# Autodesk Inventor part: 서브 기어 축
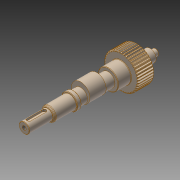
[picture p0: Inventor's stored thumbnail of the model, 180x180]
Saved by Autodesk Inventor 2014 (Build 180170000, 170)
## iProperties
Created: 2018-12
Part Number: 서브 기어 축
Material: 강철, 연강
Document SubType Name: Modeling
Designer: mduedu
Categories: <?xml version="1.0" encoding="UTF-16"?> <MemberInstance><Categories><FamilyTemplate><FamilyTemplateParameter ValueType="xs:double" Id="1" ObjectReferenceKey="da
Density: 7.86 g/cm^3
Mass: 484.999 g
Surface Area: 155.103 cm^2
Volume: 61.7047 cm^3
Appearance: 기본값(1)
Author: mduedu
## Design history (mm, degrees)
sketch "Sketch1"
  geometry: C1 r 21.3 at (0, 0)
  constraints: 1 centre point
  dimensions: "d0" = 42.6 diameter of C1 (= da_da)
extrude "Extrusion1" new body sketch "Sketch1" distance "d1" = 20 (= da_b); taper "d2" = 0 deg
workplane "Work Plane2"
sketch "Sketch2"
  geometry: C1 r 21.3 at (0, 0) reference; C2 r 20.5 at (0, 0)
  constraints: 1 centre point, 1 coincident
  dimensions: "d3" = 41 diameter of C2 (= da_dw)
feature "피치 지름" sketch "Sketch2" dims "d4" = 10, "d5" = 0
workplane "Work Plane8"
workplane "Work Plane9"
chamfer "모따기1" distance "d49" = 1; stored, may be unused: second distance "d50" = 2, angle "d51" = 45 deg
sketch "스케치3"
  geometry: C1 r 12.5 at (0, 0); 1 further point
  constraints: 1 centre point, 1 coincident
  dimensions: "d52" = 25 diameter of C1
extrude "돌출2" join sketch "스케치3" distance "d53" = 16; taper "d54" = 0 deg
sketch "스케치4"
  geometry: C1 r 8.5 at (0, 0); 1 further point
  constraints: 1 centre point, 1 coincident
  dimensions: "d55" = 17 diameter of C1
extrude "돌출3" join sketch "스케치4" distance "d56" = 104; taper "d57" = 0 deg
sketch "스케치5"
  geometry: C1 r 7.5 at (0, 0); 1 further point
  constraints: 1 centre point, 1 coincident
  dimensions: "d58" = 15 diameter of C1
extrude "돌출4" join sketch "스케치5" distance "d59" = 16; taper "d60" = 0 deg
sketch "스케치6"
  geometry: C1 r 4 at (0, 0); 1 further point
  constraints: 1 centre point, 1 coincident
  dimensions: "d61" = 8 diameter of C1
extrude "돌출5" join sketch "스케치6" distance "d62" = 7; taper "d63" = 0 deg
fillet "모깎기1" dims "d67" = 0.5
feature "스퍼 기어" dims "da_b" = 20, "da_d" = 41, "da_aw" = 31, "da_da" = 42.6, "da_df" = 39.086, "da_dw" = 41, angle "da_beta" = 0 deg, "da_lefttooth" = 0, "da_righttooth" = 0
node "작업 평면11"
sketch "스케치7"
  geometry: C1 r 11.5 at (0, 3); C2 r 8.5 at (0, 0) reference; 1 further point
  constraints: 1 centre point, 1 tangent, 1 vertical alignment
  dimensions: "d69" = 3 distance of point (0, 0) C1.centre; "d70" = 23 diameter of C1 (derived)
extrude "돌출6" join sketch "스케치7" stored distance "d71" = 20; taper "d72" = 0 deg
node "작업 평면12"
sketch "스케치8"
  geometry: C1 r 12.5 at (0, 0) reference; C2 r 10 at (0, 0); 1 further point
  constraints: 1 centre point, 1 coincident
  dimensions: "d110" = 20 diameter of C2
extrude "돌출7" join sketch "스케치8" distance "d74" = 5; taper "d75" = 0 deg
sketch "스케치14"
  geometry: L1 (-11.5, 111)-(-6.5, 111); L2 (-6.5, 111)-(-6.5, 140); L3 (-6.5, 140)-(-11.5, 140); L4 (-11.5, 140)-(-11.5, 111); L5 (8.5, 140)-(-8.5, 140) reference; L6 (0, 0)-(0, 140)
  constraints: 10 end point, 2 parallel, 1 collinear, 1 horizontal, 1 midpoint, 1 perpendicular
  dimensions: "d92" = 29 distance between parallel lines of L1 L5; "d93" = 13 diameter of L2 L6; "d95" = 5 distance of L2.end L3.end
revolve "회전2" sketch "스케치14" stored, may be unused: angle "d96" = 90 deg
chamfer "모따기4" distance "d97" = 0.5; stored, may be unused: second distance "d98" = 2, angle "d99" = 45 deg
node "작업 평면13"
sketch "스케치11"
  geometry: L1 (-2.5, 9)-(-2.5, -10); L2 (2.5, -10)-(2.5, 9); L3 (-6, 14.5)-(6, 14.5) reference; A1 r 2.5 centre (0, 9) between (2.5, 9) and (-2.5, 9); A2 r 2.5 centre (0, -10) between (-2.5, -10) and (2.5, -10); 1 further point
  constraints: 4 end point, 4 point on circle, 4 tangent, 2 centre point, 2 vertical alignment, 1 parallel
  dimensions: "d84" = 24 dimension on A2 A1; "d85" = 5 distance between parallel lines of L1 L2; "d108" = 3 distance edge to line of A1 L3
extrude "돌출8" cut sketch "스케치11" distance "d86" = 3; taper "d87" = 0 deg
sketch "스케치12" dims "d88" = 32
  geometry: C1 r 0.5 at (0, -16); 2 further points
  constraints: 2 vertical alignment, 1 centre point, 1 coincident, 2 other
  dimensions: "d89" = 1 diameter of C1
extrude "돌출9" join sketch "스케치12" distance "d90" = 0.3; taper "d91" = 0 deg
sketch "스케치13"
  geometry: C1 r 11.5 at (0, 3) reference; 1 further point
  node "절단 모서리 투영1"
sketch "스케치15"
  geometry: L1 (-8.5, 109.181)-(-7.45, 111); L2 (-8.5, 111)-(8.5, 111) reference; L3 (-8.5, 84)-(-8.5, 111) reference; L4 (0, 0)-(0, 111); L5 (-7.45, 111)-(-8.5, 111); L6 (-8.5, 109.181)-(-8.5, 111)
  constraints: 8 end point, 2 collinear, 2 point on line, 1 midpoint
  dimensions: "d103" = 14.9 diameter of L1.end L4; "d104" = 30 deg angle of L3 L1
revolve "회전3" sketch "스케치15" stored, may be unused: angle "d105" = 90 deg
fillet "모깎기2" dims "d106" = 2
fillet "모깎기3" dims "d107" = 1
chamfer "모따기5" distance "d112" = 0.5; stored, may be unused: second distance "d113" = 2, angle "d114" = 45 deg
hole "구멍1" diameter "d117" = 4.917; stored, may be unused: countersink angle "d121" = 90 deg, drill point angle "d123" = 118 deg; dims "d118" = 12, "d119" = 4, "d120" = 2, "d122" = 14, "d124" = 10, "d125" = 10
body "Solid1"
body "Srf1"
node "투영된 루프1"
other parameters: "d16" = 31 (= da_aw), "d17" = 0, "d34" = 0.76624 (computed from da_z), "d39" = 0, "d41" = 0, "d43" = 31 (= da_aw), "d46" = 31 (= da_aw), "d47" = 0, "d48" = 0
